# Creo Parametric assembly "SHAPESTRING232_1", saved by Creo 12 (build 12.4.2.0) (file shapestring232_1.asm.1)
Units: Custom; MM, KILOGRAM, SECS

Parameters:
  PTC_WM_ITERATION = "0"
  PTC_WM_VERSION = "-.0"
  PTC_WM_LIFECYCLE_STATE = "In Work"
  PTC_WM_LIFECYCLE = "MO_CADDocument"
  PTC_WM_CREATED_BY = "Maximilian Roepper (Z0017RMS: MO)"
  PTC_WM_CREATED_ON = "18-Sep-26 11:36:42 AM"
  PTC_WM_MODIFIED_BY = "Maximilian Roepper (Z0017RMS: MO)"
  PTC_WM_MODIFIED_ON = "18-Sep-26 11:36:46 AM"
  PDMLINKNUMBER = "PDM000071455172"
  PTC_WM_NAME = "shapestring232_1.asm"
  PTC_WM_NUMBER = "PDM000071455172"

Other parameters: WEIGHT, WEIGHT_FACTOR, WEIGHT_ADD, MC_ERRORS, SUPPLIER, ISPOSITIONINGASSEMBLY

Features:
  1. coordinate system
  2. imported feature
  3. component "SHAPESTRING091_1"
  4. component "SHAPESTRING231_1"

Other named items: DRW_VIEW_ORG, ROUGH-GROB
